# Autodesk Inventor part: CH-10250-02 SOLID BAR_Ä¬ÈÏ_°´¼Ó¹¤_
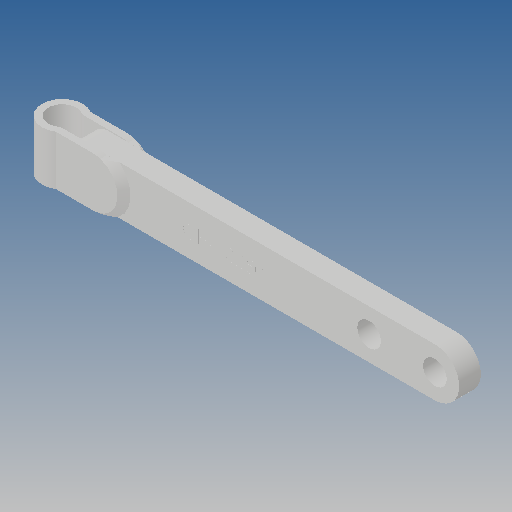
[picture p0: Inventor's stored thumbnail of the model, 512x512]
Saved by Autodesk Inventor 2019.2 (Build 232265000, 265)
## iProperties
Created: 2012-09
Part Number: CH-10250-02 SOLID BAR_Ä¬ÈÏ_°´¼Ó¹¤_
Material: Ogólny
Document SubType Name: Modeling
Designer: CADENGINEERING4
Density: 1 g/cm^3
Appearance: Domyślna
Author: CADENGINEERING4
Revision Number: ÈÎºÎ
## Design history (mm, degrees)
feature "ÇÐ³ý-À­Éì4"
feature "Ô²½Ç1"
feature "Ô²½Çº¸·ì4"
feature "Ô²½Çº¸·ì5"
node "Bryła1"
node "Bryła2"
node "Bryła3"
node "Bryła4"
